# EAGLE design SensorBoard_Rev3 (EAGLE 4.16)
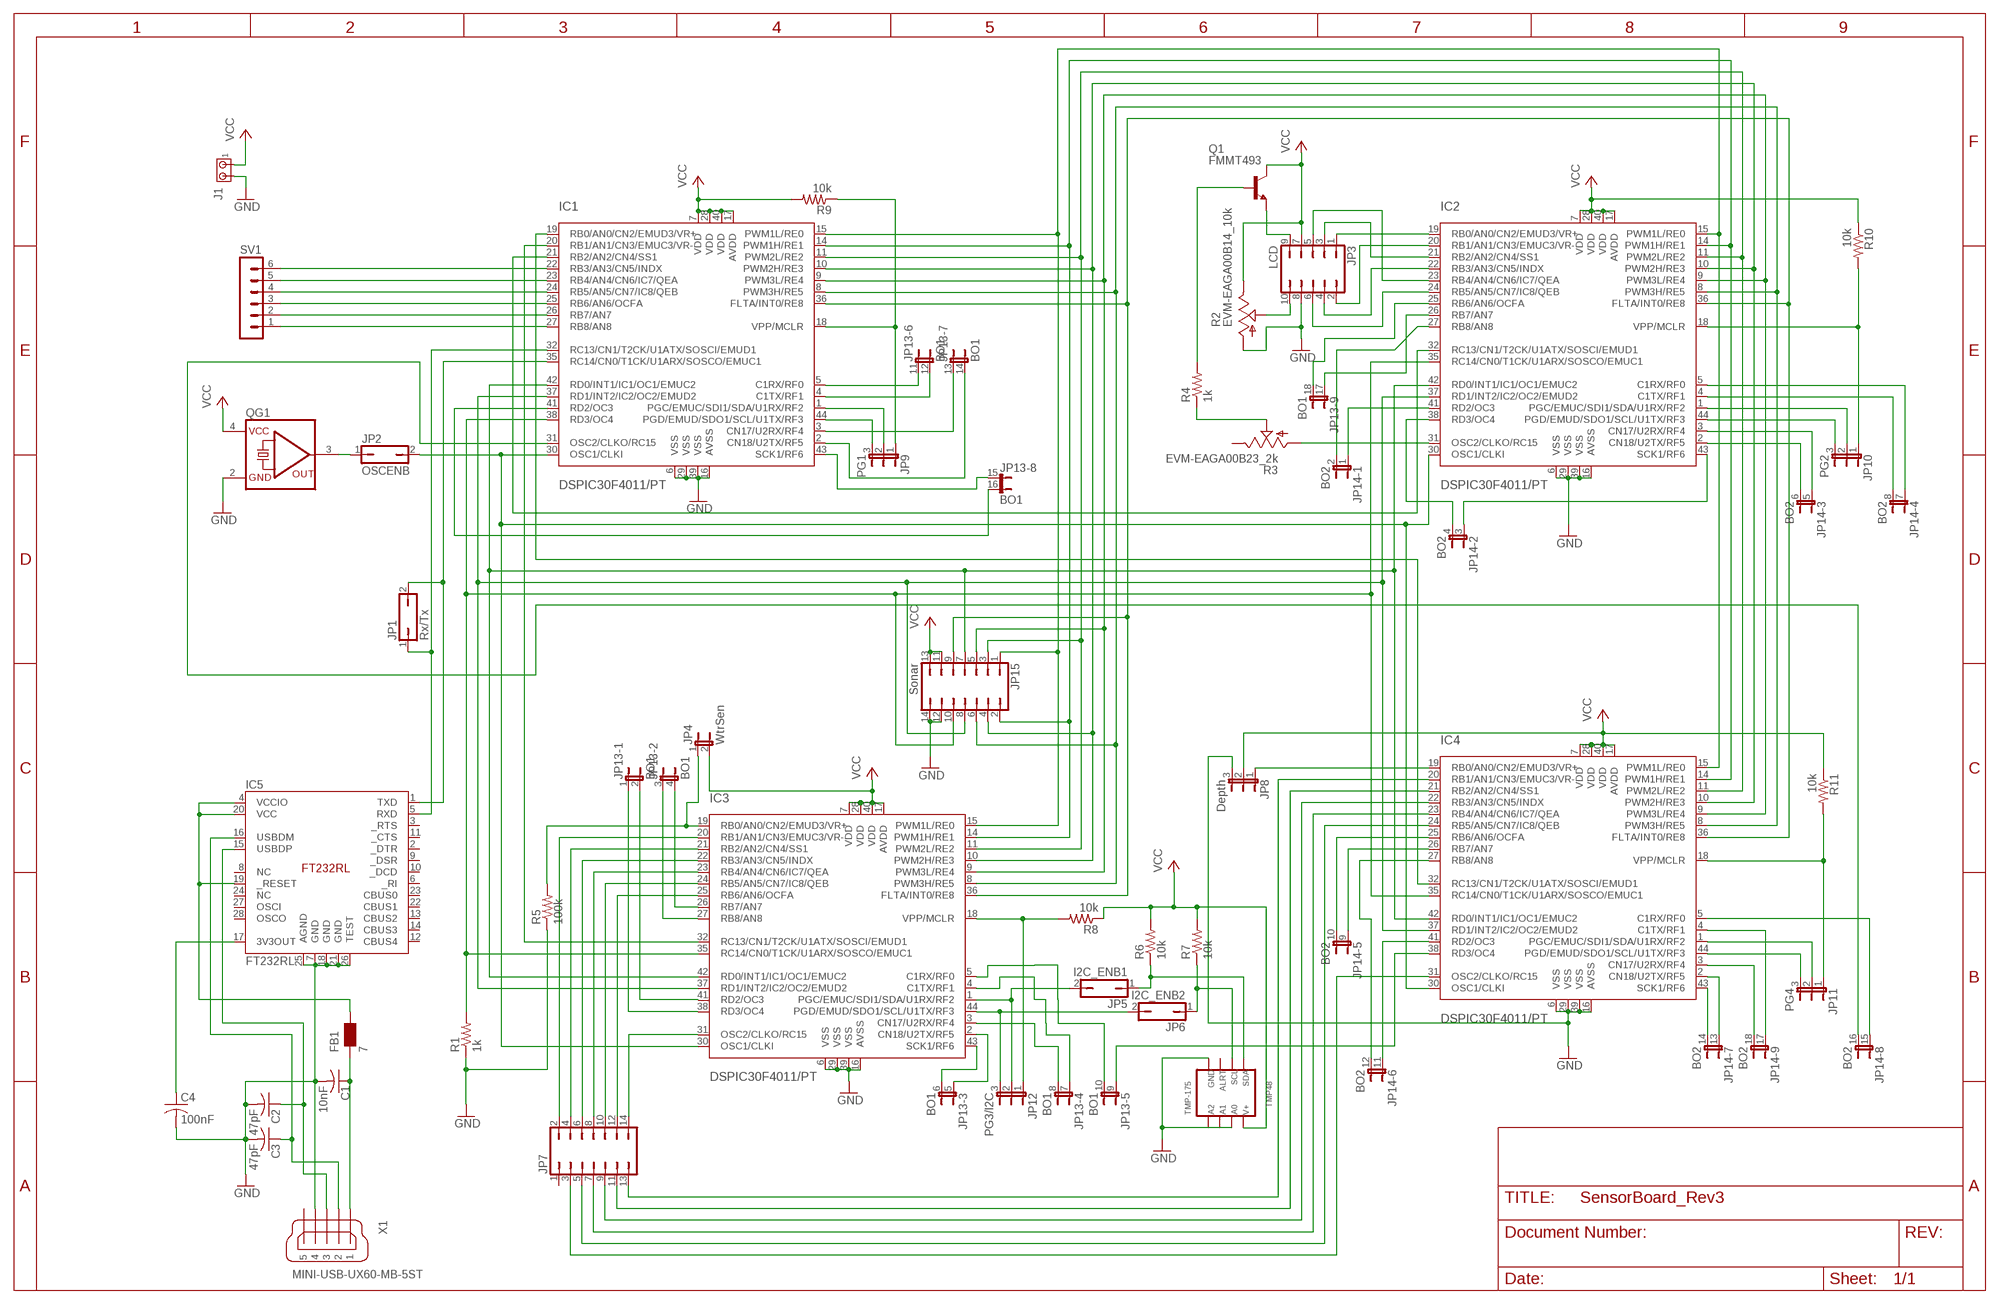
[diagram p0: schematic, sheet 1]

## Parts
C1  10nF  C-USC1206K  [C1206K]
C2  47pF  C-USC1206K  [C1206K]
C3  47pF  C-USC1206K  [C1206K]
C4  100nF  C-USC1206K  [C1206K]
FB1  7  WE-CBF_0805  [0805]
IC1  DSPIC30F4011/PT  [TQFP44]
IC2  DSPIC30F4011/PT  [TQFP44]
IC3  DSPIC30F4011/PT  [TQFP44]
IC4  DSPIC30F4011/PT  [TQFP44]
IC5  FT232RL  [SSOP-28]
J1  MTA02-156  [1X2MTA]
JP1  Rx/Tx  JP1Q  [JP1]
JP2  OSCENB  JP1Q  [JP1]
JP3  LCD  JP5Q  [JP5Q]
JP4  WtrSen  JP1E  [JP1]
JP5  I2C_ENB1  JP1Q  [JP1]
JP6  I2C_ENB2  JP1Q  [JP1]
JP7  JP7Q  [JP7Q]
JP8  Depth  JP2E  [JP2]
JP9  PG1  JP2E  [JP2]
JP10  PG2  JP2E  [JP2]
JP11  PG4  JP2E  [JP2]
JP12  PG3/I2C  JP2E  [JP2]
JP13  BO1  JP9QE  [JP9Q]
JP14  BO2  JP9QE  [JP9Q]
JP15  Sonar  JP7Q  [JP7Q]
Q1  FMMT493  -NPN-SOT23-EBC  [SOT23-EBC]
QG1  SG531  [DIL08-4]
R1  1k  R-US_R1206  [R1206]
R2  EVM-EAGA00B14_10k  TRIM_US-CT6  [CT6]
R3  EVM-EAGA00B23_2k  TRIM_US-CT6  [CT6]
R4  1k  R-US_R1206  [R1206]
R5  100k  R-US_R1206  [R1206]
R6  10k  R-US_R1206  [R1206]
R7  10k  R-US_R1206  [R1206]
R8  10k  R-US_R1206  [R1206]
R9  10k  R-US_R1206  [R1206]
R10  10k  R-US_R1206  [R1206]
R11  10k  R-US_R1206  [R1206]
SV1  MA06-1  [MA06-1]
TMP48  TMP-175  [SO-08]
X1  MINI-USB-UX60-MB-5ST  [UX60-MB-5ST]

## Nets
GND [4amps]: C1.2 C2.2 C3.2 C4.2 IC1.6(VSS) IC1.16(AVSS) IC1.29(VSS) IC1.39(VSS) IC2.6(VSS) IC2.16(AVSS) IC2.29(VSS) IC2.39(VSS) IC3.6(VSS) IC3.16(AVSS) IC3.29(VSS) IC3.39(VSS) IC4.6(VSS) IC4.16(AVSS) IC4.29(VSS) IC4.39(VSS) IC5.7(GND) IC5.18(GND) IC5.21(GND) IC5.25(AGND) IC5.26(TEST) J1.2 JP3.8 JP8.3 JP15.12 JP15.14 QG1.2(GND) R1.1 R2.A R5.1 TMP48.4 TMP48.5 TMP48.6 TMP48.7 X1.4
N$1: IC1.19(RB0/AN0/CN2/EMUD3/VR+) IC4.32(RC13/CN1/T2CK/U1ATX/SOSCI/EMUD1)
N$2: IC1.20(RB1/AN1/CN3/EMUC3/VR-) IC3.32(RC13/CN1/T2CK/U1ATX/SOSCI/EMUD1)
N$3: IC1.21(RB2/AN2/CN4/SS1) IC2.32(RC13/CN1/T2CK/U1ATX/SOSCI/EMUD1)
N$4: IC1.22(RB3/AN3/CN5/INDX) SV1.6
N$5: IC1.24(RB5/AN5/CN7/IC8/QEB) SV1.4
N$6: IC1.25(RB6/AN6/OCFA) SV1.3
N$7: IC1.26(RB7/AN7) SV1.2
N$8: IC1.27(RB8/AN8) SV1.1
N$9: IC1.30(OSC1/CLKI) IC2.30(OSC1/CLKI) IC3.30(OSC1/CLKI) IC4.30(OSC1/CLKI) JP2.2
N$10: C2.1 IC5.15(USBDP) X1.3
N$11: C1.1 FB1.1 X1.1
N$12: C3.1 IC5.16(USBDM) X1.2
N$13: C4.1 IC5.17(3V3OUT)
N$14: FB1.2 IC5.4(VCCIO) IC5.19(_RESET) IC5.20(VCC)
N$15: IC1.32(RC13/CN1/T2CK/U1ATX/SOSCI/EMUD1) IC5.5(RXD) JP1.1
N$16: IC1.35(RC14/CN0/T1CK/U1ARX/SOSCO/EMUC1) IC5.1(TXD) JP1.2
N$17: JP2.1 QG1.3(OUT)
N$18: IC1.23(RB4/AN4/CN6/IC7/QEA) SV1.5
N$19: IC1.15(PWM1L/RE0) IC2.15(PWM1L/RE0) IC3.15(PWM1L/RE0) IC4.15(PWM1L/RE0) JP15.1
N$20: IC1.14(PWM1H/RE1) IC2.14(PWM1H/RE1) IC3.14(PWM1H/RE1) IC4.14(PWM1H/RE1) JP15.2
N$21: IC1.11(PWM2L/RE2) IC2.11(PWM2L/RE2) IC3.11(PWM2L/RE2) IC4.11(PWM2L/RE2) JP15.3
N$22: IC1.10(PWM2H/RE3) IC2.10(PWM2H/RE3) IC3.10(PWM2H/RE3) IC4.10(PWM2H/RE3) JP15.4
N$23: IC1.9(PWM3L/RE4) IC2.9(PWM3L/RE4) IC3.9(PWM3L/RE4) IC4.9(PWM3L/RE4) JP15.5
N$24: IC1.8(PWM3H/RE5) IC2.8(PWM3H/RE5) IC3.8(PWM3H/RE5) IC4.8(PWM3H/RE5) JP15.6
N$25: IC1.42(RD0/INT1/IC1/OC1/EMUC2) IC2.42(RD0/INT1/IC1/OC1/EMUC2) IC3.42(RD0/INT1/IC1/OC1/EMUC2) IC4.42(RD0/INT1/IC1/OC1/EMUC2) JP15.7
N$26: IC1.37(RD1/INT2/IC2/OC2/EMUD2) IC2.37(RD1/INT2/IC2/OC2/EMUD2) IC3.37(RD1/INT2/IC2/OC2/EMUD2) IC4.37(RD1/INT2/IC2/OC2/EMUD2) JP15.8
N$27: IC1.38(RD3/OC4) IC2.35(RC14/CN0/T1CK/U1ARX/SOSCO/EMUC1) IC3.35(RC14/CN0/T1CK/U1ARX/SOSCO/EMUC1) IC4.35(RC14/CN0/T1CK/U1ARX/SOSCO/EMUC1) JP15.10 R1.2
N$28: IC1.36(FLTA/INT0/RE8) IC2.36(FLTA/INT0/RE8) IC3.36(FLTA/INT0/RE8) IC4.36(FLTA/INT0/RE8) JP15.9
N$29: IC2.19(RB0/AN0/CN2/EMUD3/VR+) JP3.1
N$30: IC2.20(RB1/AN1/CN3/EMUC3/VR-) JP3.2
N$31: IC2.21(RB2/AN2/CN4/SS1) JP3.3
N$32: IC2.22(RB3/AN3/CN5/INDX) JP3.4
N$33: IC2.23(RB4/AN4/CN6/IC7/QEA) JP3.5
N$34: IC2.24(RB5/AN5/CN7/IC8/QEB) JP3.6
N$35: JP3.10 R2.S
N$36: IC2.31(OSC2/CLKO/RC15) R3.A
N$37: R3.S R4.1
N$38: JP3.9 Q1.E
N$39: Q1.B R4.2
N$40: IC3.21(RB2/AN2/CN4/SS1) JP7.4
N$41: IC3.19(RB0/AN0/CN2/EMUD3/VR+) JP4.1 R5.2
N$42: IC3.22(RB3/AN3/CN5/INDX) JP7.6
N$43: JP6.1 R7.1 TMP48.2
N$44: JP5.1 R6.1 TMP48.1
N$45: IC3.1(PGC/EMUC/SDI1/SDA/U1RX/RF2) JP5.2 JP12.2
N$46: IC3.44(PGD/EMUD/SDO1/SCL/U1TX/RF3) JP6.2 JP12.3
N$47: IC3.23(RB4/AN4/CN6/IC7/QEA) JP7.8
N$48: IC3.24(RB5/AN5/CN7/IC8/QEB) JP7.10
N$49: IC3.25(RB6/AN6/OCFA) JP7.12
N$50: IC3.20(RB1/AN1/CN3/EMUC3/VR-) JP7.2
N$51: IC3.31(OSC2/CLKO/RC15) JP7.14
N$52: IC4.19(RB0/AN0/CN2/EMUD3/VR+) JP8.1
N$53: IC4.20(RB1/AN1/CN3/EMUC3/VR-) JP7.13
N$54: IC4.21(RB2/AN2/CN4/SS1) JP7.11
N$55: IC4.22(RB3/AN3/CN5/INDX) JP7.9
N$56: IC4.23(RB4/AN4/CN6/IC7/QEA) JP7.7
N$57: IC4.24(RB5/AN5/CN7/IC8/QEB) JP7.5
N$58: IC4.31(OSC2/CLKO/RC15) JP7.3
N$59: IC3.18(VPP/MCLR) JP12.1 R8.2
N$60: IC1.18(VPP/MCLR) JP9.1 R9.1
N$61: IC2.18(VPP/MCLR) JP10.1 R10.2
N$62: IC1.1(PGC/EMUC/SDI1/SDA/U1RX/RF2) JP9.2
N$63: IC1.44(PGD/EMUD/SDO1/SCL/U1TX/RF3) JP9.3
N$64: IC2.1(PGC/EMUC/SDI1/SDA/U1RX/RF2) JP10.2
N$65: IC2.44(PGD/EMUD/SDO1/SCL/U1TX/RF3) JP10.3
N$66: IC4.18(VPP/MCLR) JP11.1 R11.2
N$67: IC4.1(PGC/EMUC/SDI1/SDA/U1RX/RF2) JP11.2
N$68: IC4.44(PGD/EMUD/SDO1/SCL/U1TX/RF3) JP11.3
N$69: IC3.38(RD3/OC4) JP13.1
N$70: IC3.41(RD2/OC3) JP13.2
N$71: IC3.27(RB8/AN8) JP13.3
N$72: IC3.26(RB7/AN7) JP13.4
N$73: IC3.2(CN18/U2TX/RF5) JP13.5
N$74: IC3.43(SCK1/RF6) JP13.6
N$75: IC3.4(C1TX/RF1) JP13.7
N$76: IC3.3(CN17/U2RX/RF4) JP13.8
N$77: IC3.5(C1RX/RF0) JP13.10
N$78: IC1.43(SCK1/RF6) JP13.15
N$79: IC1.2(CN18/U2TX/RF5) JP13.14
N$80: IC1.3(CN17/U2RX/RF4) JP13.13
N$81: IC1.4(C1TX/RF1) JP13.12
N$82: IC1.5(C1RX/RF0) JP13.11
N$83: IC1.41(RD2/OC3) JP13.16
N$84: IC2.25(RB6/AN6/OCFA) JP13.18
N$85: IC2.26(RB7/AN7) JP13.17
N$86: IC2.27(RB8/AN8) JP14.2
N$87: IC2.41(RD2/OC3) JP14.1
N$88: IC2.38(RD3/OC4) JP14.4
N$89: IC2.43(SCK1/RF6) JP14.3
N$90: IC2.2(CN18/U2TX/RF5) JP14.6
N$91: IC2.3(CN17/U2RX/RF4) JP14.5
N$92: IC2.5(C1RX/RF0) JP14.7
N$93: IC2.4(C1TX/RF1) JP14.8
N$94: IC4.25(RB6/AN6/OCFA) JP14.10
N$95: IC4.26(RB7/AN7) JP14.9
N$96: IC4.27(RB8/AN8) JP14.12
N$97: IC4.41(RD2/OC3) JP14.11
N$98: IC4.43(SCK1/RF6) JP14.14
N$99: IC4.2(CN18/U2TX/RF5) JP14.13
N$100: IC4.3(CN17/U2RX/RF4) JP14.18
N$101: IC4.4(C1TX/RF1) JP14.17
N$102: IC4.5(C1RX/RF0) JP14.15
N$103: IC4.38(RD3/OC4) JP13.9
N$104: IC1.31(OSC2/CLKO/RC15) JP14.16
VCC [4amps]: IC1.7(VDD) IC1.17(AVDD) IC1.28(VDD) IC1.40(VDD) IC2.7(VDD) IC2.17(AVDD) IC2.28(VDD) IC2.40(VDD) IC3.7(VDD) IC3.17(AVDD) IC3.28(VDD) IC3.40(VDD) IC4.7(VDD) IC4.17(AVDD) IC4.28(VDD) IC4.40(VDD) J1.1 JP3.7 JP4.2 JP8.2 JP15.11 JP15.13 Q1.C QG1.4(VCC) R2.E R6.2 R7.2 R8.1 R9.2 R10.1 R11.1 TMP48.8
Unconnected: IC5.2(_DTR) IC5.3(_RTS) IC5.6(_RI) IC5.8(NC) IC5.9(_DSR) IC5.10(_DCD) IC5.11(_CTS) IC5.12(CBUS4) IC5.13(CBUS2) IC5.14(CBUS3) IC5.22(CBUS1) IC5.23(CBUS0) IC5.24(NC) IC5.27(OSCI) IC5.28(OSCO) JP7.1 R3.E TMP48.3 X1.5

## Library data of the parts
C1-C4 = rcl:C-US: CAPACITOR, American symbol
FB1 = wuerth-elektronik:WE-CBF: SMD EMI Suppression Ferrite Beads
IC1-IC4 = microchip-dspic:DSPIC30F4011: dsPIC Motion Controller DSC
IC5 = ftdi4:FT232RL
J1 = con-amp:MTA02-156: AMP connector
JP1 JP2 JP5 JP6 = jumper:JP1Q: JUMPER
JP3 = jumper:JP5Q: JUMPER
JP4 = jumper:JP1E: JUMPER
JP7 JP15 = jumper:JP7Q: JUMPER
JP8-JP12 = jumper:JP2E: JUMPER
JP13 JP14 = jumper:JP9QE: JUMPER
Q1 = transistor:*-NPN-: NPN Transistror
QG1 = crystal:SG531: CRYSTAL RESONATOR
R1 R4-R11 = rcl:R-US_: RESISTOR, American symbol
R2 R3 = pot:TRIM_US-: POTENTIOMETER
SV1 = con-lstb:MA06-1: PIN HEADER
TMP48 = texas:TMP-175
X1 = con-hirose:MINI-USB-: MINI USB Connector Source: http://www.hirose.co.jp/cataloge_hp/e24000019.pdf

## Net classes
0 default: width 0.178 mm
1 2amps: width 0.178 mm
2 4amps: width 0.533 mm

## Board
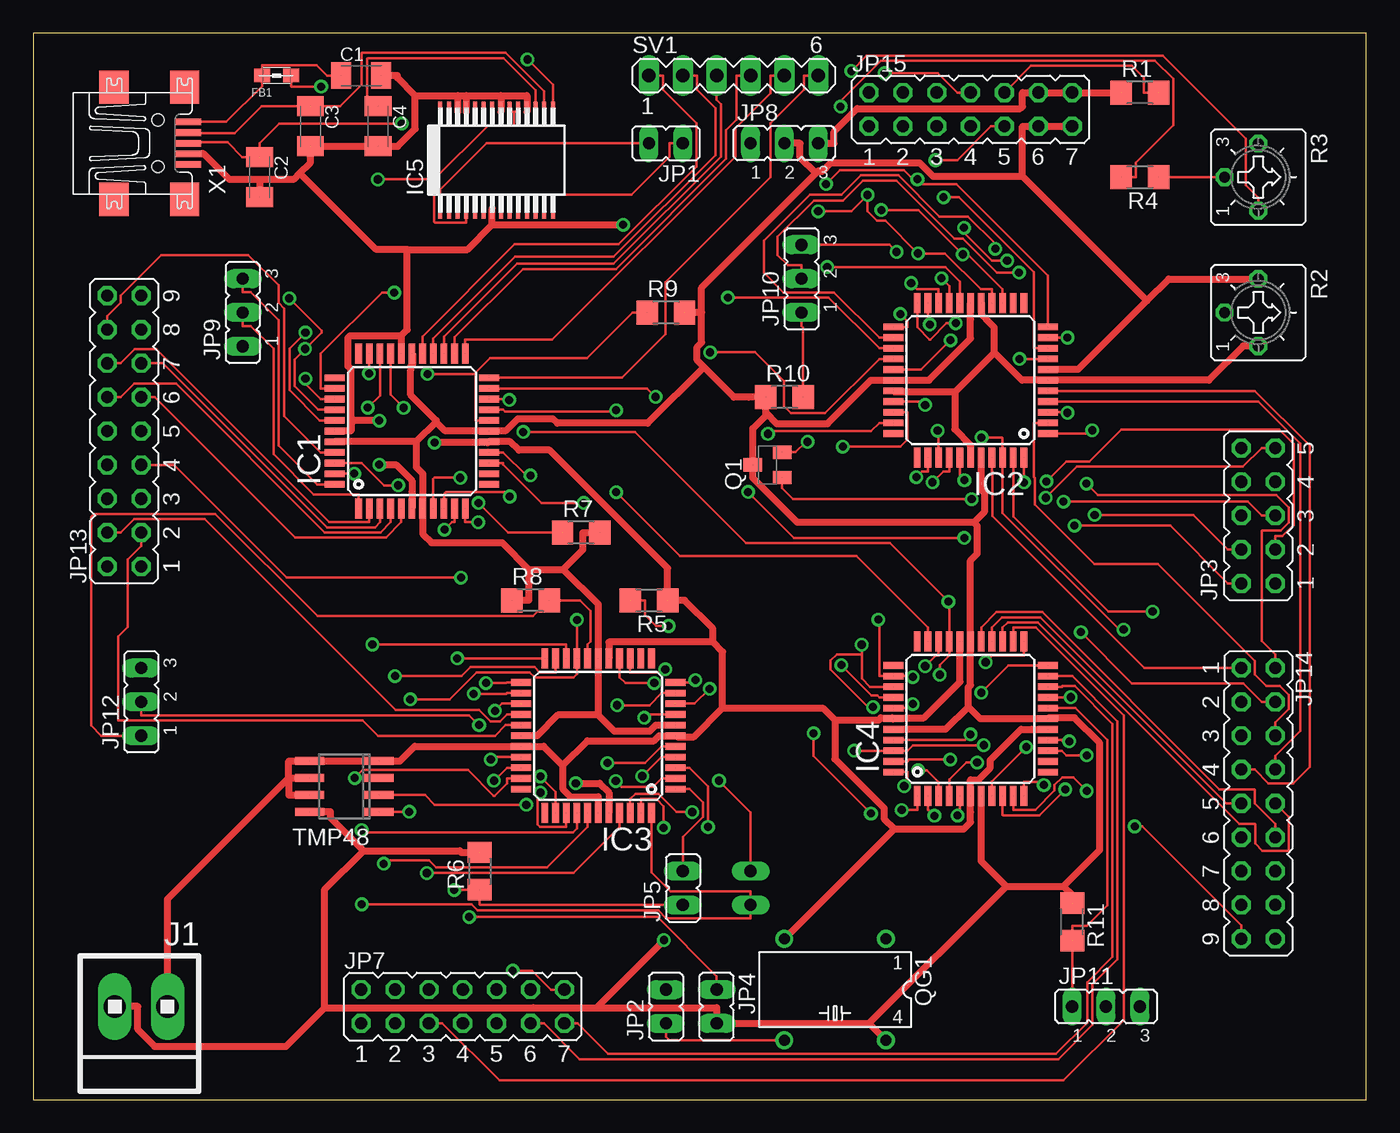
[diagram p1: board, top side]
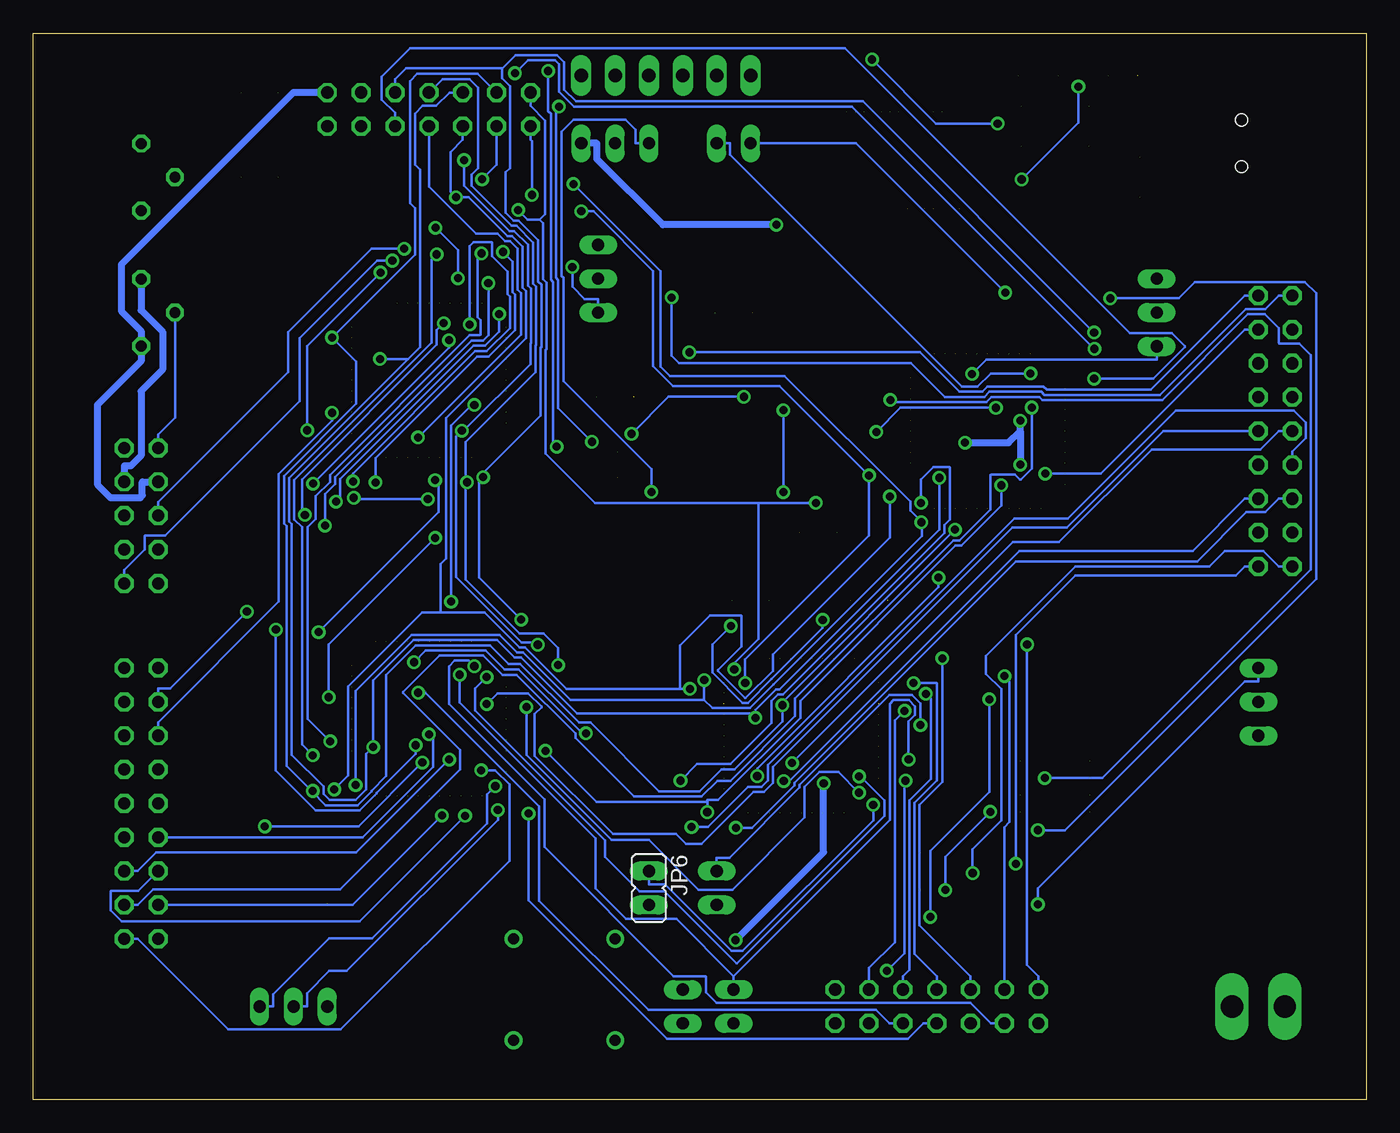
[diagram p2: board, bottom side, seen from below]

Size 100 x 80 mm. Coordinates in mm from the lower left corner, seen from the top.
Outline: 0,0 100,0 100,80 0,80 0,0
Copper layers (1*16): Top 0.035mm / dielectric 1.5mm / Bottom 0.035mm
Design rules "default": minimum track width 10mil, minimum drill 24mil, track to track 8mil, track to pad 8mil, pad to pad 8mil, via to via 8mil, smd to smd 8mil, copper to edge 40mil, drill to drill 8mil, minimum pad ring 10mil, minimum via ring 8mil, stop-mask expansion 4mil, vias tented up to drill 0mil, thermal gap 10mil

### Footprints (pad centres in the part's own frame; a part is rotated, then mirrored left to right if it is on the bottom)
C1206K = smd 1.5 x 2: 1 -1.5,0; 2 1.5,0
0805 = smd 1.2 x 1: 1 -1.1,0; 2 1.1,0
TQFP44 = smd 1.5 x 0.5: 1 -5.8,4; 2 -5.8,3.2; 3 -5.8,2.4; 4 -5.8,1.6; 5 -5.8,0.8; 6 -5.8,0; 7 -5.8,-0.8; 8 -5.8,-1.6; 9 -5.8,-2.4; 10 -5.8,-3.2; 11 -5.8,-4; 23 5.8,-4; 24 5.8,-3.2; 25 5.8,-2.4; 26 5.8,-1.6; 27 5.8,-0.8; 28 5.8,0; 29 5.8,0.8; 30 5.8,1.6; 31 5.8,2.4; 32 5.8,3.2; 33 5.8,4 | smd 0.5 x 1.5: 12 -4,-5.8; 13 -3.2,-5.8; 14 -2.4,-5.8; 15 -1.6,-5.8; 16 -0.8,-5.8; 17 0,-5.8; 18 0.8,-5.8; 19 1.6,-5.8; 20 2.4,-5.8; 21 3.2,-5.8; 22 4,-5.8; 34 4,5.8; 35 3.2,5.8; 36 2.4,5.8; 37 1.6,5.8; 38 0.8,5.8; 39 0,5.8; 40 -0.8,5.8; 41 -1.6,5.8; 42 -2.4,5.8; 43 -3.2,5.8; 44 -4,5.8
SSOP-28 = smd 0.3 x 1.5: 1 -4.225,-3.625; 2 -3.575,-3.625; 3 -2.925,-3.625; 4 -2.275,-3.625; 5 -1.625,-3.625; 6 -0.975,-3.625; 7 -0.325,-3.625; 8 0.325,-3.625; 9 0.975,-3.625; 10 1.625,-3.625; 11 2.275,-3.625; 12 2.925,-3.625; 13 3.575,-3.625; 14 4.225,-3.625; 15 4.225,3.625; 16 3.575,3.625; 17 2.925,3.625; 18 2.275,3.625; 19 1.625,3.625; 20 0.975,3.625; 21 0.325,3.625; 22 -0.325,3.625; 23 -0.975,3.625; 24 -1.625,3.625; 25 -2.275,3.625; 26 -2.925,3.625; 27 -3.575,3.625; 28 -4.225,3.625
1X2MTA = drill 1.676 long: 1 1.981,0; 2 -1.981,0
JP1 = drill 0.914 long: 1 0,-1.27; 2 0,1.27
JP5Q = drill 0.914 octagon: 1 -5.08,-1.27; 2 -5.08,1.27; 3 -2.54,-1.27; 4 -2.54,1.27; 5 0,-1.27; 6 0,1.27; 7 2.54,-1.27; 8 2.54,1.27; 9 5.08,-1.27; 10 5.08,1.27
JP7Q = drill 0.914 octagon: 1 -7.62,-1.27; 2 -7.62,1.27; 3 -5.08,-1.27; 4 -5.08,1.27; 5 -2.54,-1.27; 6 -2.54,1.27; 7 0,-1.27; 8 0,1.27; 9 2.54,-1.27; 10 2.54,1.27; 11 5.08,-1.27; 12 5.08,1.27; 13 7.62,-1.27; 14 7.62,1.27
JP2 = drill 0.914 long: 1 -2.54,0; 2 0,0; 3 2.54,0
JP9Q = drill 0.914 octagon: 1 -10.16,-1.27; 2 -10.16,1.27; 3 -7.62,-1.27; 4 -7.62,1.27; 5 -5.08,-1.27; 6 -5.08,1.27; 7 -2.54,-1.27; 8 -2.54,1.27; 9 0,-1.27; 10 0,1.27; 11 2.54,-1.27; 12 2.54,1.27; 13 5.08,-1.27; 14 5.08,1.27; 15 7.62,-1.27; 16 7.62,1.27; 17 10.16,-1.27; 18 10.16,1.27
SOT23-EBC = smd 1 x 1.4: B 0.95,-1.1; C 0,1.1; E -0.95,-1.1
DIL08-4 = drill 0.813 round: 1 -3.81,-3.81; 2 3.81,-3.81; 3 3.81,3.81; 4 -3.81,3.81
R1206 = smd 1.6 x 1.8: 1 -1.4,0; 2 1.4,0
CT6 = drill 0.813 octagon: A 2.515,0; E -2.515,0; S 0,-2.54
MA06-1 = drill 1.016 long: 1 -6.35,0; 2 -3.81,0; 3 -1.27,0; 4 1.27,0; 5 3.81,0; 6 6.35,0
SO-08 = smd 0.6 x 2.2: 1 -1.905,-2.6; 2 -0.635,-2.6; 3 0.635,-2.6; 4 1.905,-2.6; 5 1.905,2.6; 6 0.635,2.6; 7 -0.635,2.6; 8 -1.905,2.6
UX60-MB-5ST = smd 2 x 0.5: 1 2.25,1.6; 2 2.25,0.8; 3 2.25,0; 4 2.25,-0.8; 5 2.25,-1.6 | smd 2.2 x 2.5: M1 -3.3,-4.2; M2 -3.3,4.2; M3 2,4.2; M4 2,-4.2 | hole 0.9: 0,-1.75; 0,1.75

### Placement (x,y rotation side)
C1  24.6,76.83 0 top
C2  16.98,69.21 270 top
C3  20.79,73.02 270 top
C4  25.87,73.02 270 top
FB1  18.25,76.83 0 top
IC1  28.41,50.16 90 top
IC2  70.32,53.97 180 top
IC3  42.38,27.3 180 top
IC4  70.32,28.57 90 top
IC5  34.76,70.48 0 top
J1  8.09,6.98 180 top
JP1  47.46,71.75 90 top
JP2  47.46,6.98 0 top
JP3  91.91,43.81 90 top
JP4  51.27,6.98 180 top
JP5  48.73,15.87 0 top
JP6  53.81,15.87 180 bottom
JP7  32.22,6.98 0 top
JP8  56.35,71.75 0 top
JP9  15.71,59.05 90 top
JP10  57.62,61.59 90 top
JP11  80.48,6.98 0 top
JP12  8.09,29.84 90 top
JP13  6.82,50.16 90 top
JP14  91.91,22.22 270 top
JP15  70.32,74.29 0 top
Q1  55.08,47.62 90 top
QG1  60.16,8.25 180 top
R1  83.02,75.56 0 top
R2  91.91,59.05 270 top
R3  91.91,69.21 270 top
R4  83.02,69.21 180 top
R5  46.19,37.46 180 top
R6  33.49,17.14 90 top
R7  41.11,42.54 0 top
R8  37.3,37.46 0 top
R9  47.46,59.05 0 top
R10  56.35,52.7 0 top
R11  77.94,13.33 270 top
SV1  52.54,76.83 0 top
TMP48  23.33,23.49 90 top
X1  9.36,71.75 0 top

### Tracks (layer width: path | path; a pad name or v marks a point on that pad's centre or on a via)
GND  (via drill 0.61 pad 1.02)  (31 unrouted)
  Top 0.127: X1.4 11.62,70.96 12.6,70.96
  Top 0.498: 48.34,27.22 48.33,27.22 48.26,27.3 | 64.44,28.65 64.44,28.57 | 71.47,58.54 71.47,58.56 71.16,58.87 | 64.62,53.09 64.61,53.09 64.54,53.17 | 34.11,49.28 34.12,49.28 34.19,49.36
  Top 0.533: 16.98,69.03 14.73,69.03 12.79,70.96 12.6,70.96 | 16.98,69.03 16.98,68.93 | 20,69.5 19.53,69.03 16.98,69.03 | 19.16,24.12 19.16,22.86 TMP48.7 | 19.16,24.12 TMP48.6 19.16,24.12 | 19.16,24.12 19.16,25.39 TMP48.5 TMP48.4 27.5,25.39 28.61,26.5 IC3.29 38.29,26.5 39.72,25.06 | R2.A 90.78,56.54 88.21,53.97 IC2.6 74.18,53.97 72.09,56.05 | R1.1 JP15.14 JP15.12 74.22,75.56 74.22,74.53 74.04,74.35 61.81,74.35 60.07,72.62 60.07,71.75 JP8.3 | 31.83,75.33 32.48,75.33 | IC5.25 32.48,75.14 32.48,75.33 | 32.48,75.33 35.09,75.33 | IC5.21 35.09,75.14 35.09,75.33 | 35.09,75.33 37.04,75.33 IC5.18 | IC5.26 31.83,75.14 31.83,75.33 | 34.44,65.63 IC5.7 | 64.44,28.57 IC4.39 | IC3.39 42.38,22.72 40.32,22.72 39.72,23.32 39.72,25.06 | 48.26,27.3 IC3.6 46.96,27.3 46.57,26.91 41.57,26.91 39.72,25.06 | IC2.16 71.16,59.73 71.16,58.87 | IC1.39 23.83,50.16 23.83,51.17 | 28.65,75.33 31.83,75.33 | 28.65,75.33 27.32,76.66 27.32,76.83 C1.2 | 28.65,75.33 28.65,72.83 27.34,71.52 C4.2 C3.2 20.79,70.3 20,69.5 | 64.54,53.17 IC2.29 | IC4.16 74.9,27.77 74.1,27.77 71.79,25.47 71.79,24.88 70.9,23.99 70.32,23.99 IC4.6 70.32,21.55 70.32,20.8 69.82,20.3 64.59,20.3 | IC3.16 43.18,34.32 50.99,34.32 | 50.99,34.32 50.99,35.34 48.86,37.46 R5.1 47.59,39.87 38.74,48.72 36.43,48.72 35.79,49.36 IC1.16 34.19,49.36 | 16.98,68.93 C2.2 | 34.11,49.28 v30.1,49.28 | 34.44,65.63 v44.25,65.63 | IC1.6 28.41,45.58 28.41,46.44 27.21,47.63 v25.95,47.63 | 27.61,57.31 IC1.29 | 64.59,20.3 QG1.2 | 16.98,68.93 C2.2 | 27.61,57.31 28.06,57.76 28.06,63.78 | 34.44,65.63 32.58,63.78 28.06,63.78 | 28.06,63.78 25.72,63.78 20,69.5 | 16.98,68.93 C2.2 | 51.72,29.38 51.72,33.59 50.99,34.32
  Top 0.533: 23.83,51.17 23.83,54.8 23.6,55.03 23.6,57.16 23.75,57.31 27.61,57.31 | 16.98,68.93 C2.2 | 69.13,53.09 64.62,53.09 | 16.98,68.93 C2.2 | 19.16,24.12 10.07,15.04 J1.2 | 16.98,68.93 C2.2 | 69.13,53.09 69.13,50.3 70.32,49.11 IC2.39 | 16.98,68.93 C2.2 | 72.09,56.05 69.13,53.09 | 72.09,56.05 72.09,57.92 71.47,58.54 | 16.98,68.93 C2.2 | 23.83,51.17 24.07,50.94 v25.95,50.94 | 16.98,68.93 C2.2 | 16.98,68.93 C2.2 | 51.72,29.38 49.56,27.22 48.34,27.22 | 16.98,68.93 C2.2 | 16.98,68.93 C2.2 | 16.98,68.93 C2.2 | 16.98,68.93 C2.2 | 16.98,68.93 C2.2 | 16.98,68.93 C2.2 | IC4.29 69.52,31.35 66.82,28.65 64.44,28.65 63.58,28.65 63.41,28.47 60.13,28.47 | 16.98,68.93 C2.2 | 64.59,20.3 63.82,21.07 63.82,21.86 60.13,25.55 60.13,28.47 | 60.13,28.47 59.23,29.38 51.72,29.38 | 16.98,68.93 C2.2 | 16.98,68.93 C2.2
  Bottom 0.533: JP15.14 80.49,75.56 93.4,62.65 93.4,59.16 91.91,57.67 R2.A 91.91,55.4 95.2,52.11 95.2,46.15 94.22,45.17 91.98,45.17 91.82,45.32 91.82,46.35 JP3.8 | JP8.3 57.71,71.75 57.71,70.57 52.77,65.63 v44.25,65.63 | 25.95,50.17 v25.95,47.63 | 25.95,50.17 26.83,49.28 v30.1,49.28 | 25.95,50.17 v25.95,50.94
N$1  (via drill 0.61 pad 1.02)  (2 unrouted)
  Top 0.178: IC1.19 35.25,51.76 35.39,51.63 43.62,51.63 v43.72,51.73 | IC4.32 67.12,35.41 61.74,40.79 48.5,40.79 v43.72,45.57
  Bottom 0.178: v43.72,45.57 v43.72,51.73
N$2  (via drill 0.61 pad 1.02)  (2 unrouted)
  Top 0.178: v35.7,52.48 35.62,52.56 IC1.20 | v24.11,24.12 24.71,24.72 32.61,24.72 34.54,22.79 34.59,22.79 35.54,23.73 35.54,24.1 IC3.32
  Bottom 0.178: v24.11,24.12 19.8,24.12 4.14,39.78 4.14,55.86 5.01,56.73 6.51,56.73 6.56,56.78 6.56,57.87 7.61,58.93 8.87,58.93 15.31,52.48 24.29,52.48 24.52,52.72 28.11,52.72 28.49,52.34 35.55,52.34 v35.7,52.48
N$3  (via drill 0.61 pad 1.02)  (2 unrouted)
  Top 0.178: IC2.32 63.48,50.77 62.86,50.15 55.32,50.15 v55.12,49.95 | IC1.21 46.05,53.36 v46.69,52.73
  Bottom 0.178: v55.12,49.95 52.34,52.73 v46.69,52.73
N$4  (1 unrouted)
  Top 0.178: IC1.22 44.16,54.16 47.44,57.45 47.44,61.34 55.32,69.21 55.32,73.26 57.83,75.77 57.83,76.83 SV1.6
N$5  (1 unrouted)
  Top 0.178: SV1.4 52.75,76.83 52.75,73.5 51.97,72.72 51.97,70.59 43.7,62.32 36.74,62.32 31.61,57.2 IC1.24
N$6  (1 unrouted)
  Top 0.178: SV1.3 51.27,75.01 51.59,74.69 51.59,70.75 43.55,62.71 36.28,62.71 30.81,57.24 IC1.25
N$7  (1 unrouted)
  Top 0.178: SV1.2 49.79,76.83 49.79,75.77 51.17,74.39 51.17,70.87 43.52,63.23 36.13,63.23 30.01,57.1 IC1.26
N$8  (1 unrouted)
  Top 0.178: SV1.1 47.25,76.83 47.25,75.77 49.75,73.27 49.75,69.99 43.92,64.17 36.12,64.17 29.21,57.26 IC1.27
N$9  (via drill 0.61 pad 1.02)  (4 unrouted)
  Top 0.178: IC3.30 34.51,25.7 v34.33,25.51 | v36.75,50.08 45.13,50.08 53.46,41.75 64.27,41.75 v68.66,37.37 68.72,37.3 IC4.30 68.72,33.33 68.01,32.62 v68.01,31.88 | IC1.30 26.81,52.88 v27.78,51.9 | IC2.30 66.65,52.37 v66.91,52.11
  Bottom 0.178: JP2.2 47.46,9.26 | JP2.2 47.46,9.26 | JP2.2 47.46,9.26 | v34.33,25.51 34.33,28.35 33.84,28.84 33.84,29.5 34.31,29.97 35.46,29.97 35.75,29.68 35.75,20.97 47.46,9.26 | v36.75,50.08 34.93,51.9 v27.78,51.9 | v68.66,37.37 68.66,50.57 67.11,52.11 v66.91,52.11 | 47.46,9.26 51.75,13.55 55.52,13.55 57.82,15.85 57.82,19.6 68.01,29.8 v68.01,31.88
N$10  (via drill 0.61 pad 1.02)  (2 unrouted)
  Top 0.127: X1.3 11.47,71.82 11.87,71.82
  Top 0.178: 11.87,71.82 14.58,71.82 15.69,70.71 C2.1 16.98,71.75 18.45,73.23 v27.64,73.23 | IC5.15 38.98,76.13 v37.08,78.04
  Bottom 0.178: v27.64,73.23 32.26,73.23 v37.08,78.04
N$11  (2 unrouted)
  Top 0.127: X1.1 11.62,73.37 12.57,73.37
  Top 0.178: 12.57,73.37 14.49,73.37 17.15,76.03 FB1.1 17.15,77.62 21.26,77.62 22.05,76.83 C1.1
N$12  (2 unrouted)
  Top 0.127: X1.2 11.4,72.51 11.83,72.51
  Top 0.178: 11.83,72.51 15.12,72.51 17.13,74.52 19.49,74.52 C3.1 23.02,74.52 24.64,76.14 24.64,78.51 24.68,78.56 35.42,78.56 38.33,75.65 IC5.16
N$13  (2 unrouted)
  Top 0.178: C4.1 25.04,75.35 25.04,78.08 25.11,78.14 35.28,78.14 37.69,75.73 IC5.17
N$14  (via drill 0.61 pad 1.02)  (4 unrouted)
  Top 0.178: 36.06,74.1 IC5.20 | 36.06,74.1 IC5.19 | IC5.4 32.48,65.81 30.13,65.81 30.09,65.86 30.09,69.04 | 30.09,69.04 34.1,73.06 36.01,73.06 36.06,73.11 36.06,74.1 | v21.59,76.01 19.38,76.01 19.35,76.03 FB1.2 | v25.85,69.04 30.09,69.04
  Bottom 0.178: v21.59,76.01 21.59,73.29 v25.85,69.04
N$15  (via drill 0.61 pad 1.02)  (2 unrouted)
  Top 0.178: JP1.1 47.72,71.75 47.72,70.74 44.88,67.9 33.13,67.9 IC5.5 | v25.18,54.48 25.21,54.51 IC1.32
  Bottom 0.178: v25.18,54.48 28.16,54.48 29.15,53.49 30.33,53.49 47.72,70.88 47.72,71.75 JP1.1
N$16  (via drill 0.61 pad 1.02)  (2 unrouted)
  Top 0.178: JP1.2 34.02,71.75 30.54,68.27 IC5.1 | IC1.35 21.57,53.36 21.57,55.96 26.15,60.54 v27.08,60.54
  Bottom 0.178: v27.08,60.54 38.29,71.75 JP1.2
N$17
  Top 0.178: QG1.3 47.72,4.44 47.46,4.7 JP2.1
N$18  (1 unrouted)
  Top 0.178: SV1.5 55.29,76.83 55.29,75.5 52.67,72.88 52.67,70.75 38.92,57 32.41,57 IC1.23
N$19  (via drill 0.61 pad 1.02)  (4 unrouted)
  Top 0.178: IC2.15 71.92,60.81 71.08,60.81 68.4,63.49 v66.38,63.49 63.93,65.94 63.3,65.94 62.59,66.64 v62.59,67.87 61.37,66.65 v58.89,66.65 | v37.3,46.83 36.99,46.83 35.25,48.56 IC1.15 | v77.72,26.88 77.26,26.88 77.16,26.97 IC4.15 | v46.59,31.25 44.42,31.25 43.98,31.68 IC3.15
  Bottom 0.178: v46.59,31.25 46.59,33.03 37.3,42.32 v37.3,46.83 44.01,53.53 52.01,53.53 53.5,55.02 53.5,62.17 57.97,66.65 v58.89,66.65 | v62.59,67.87 62.59,71.91 62.7,72.01 JP15.1 | v66.38,63.49 66.67,63.19 66.67,58.69 66.46,58.48 66.46,57.39 66.51,57.34 67.27,57.34 77.75,46.86 77.75,46.34 78.82,45.27 78.82,43.54 79.41,42.95 79.41,28.56 v77.72,26.88
N$20  (via drill 0.61 pad 1.02)  (4 unrouted)
  Top 0.178: IC1.14 35.25,47.76 35.25,47.64 38.12,44.77 v41.29,44.77 | IC3.14 44.78,32.05 47.19,32.05 v47.41,32.27 | IC4.14 77.16,26.17 77.51,25.82 v79.03,25.82 | IC2.14 72.72,60.81 70.12,63.41 v69.73,63.41 66.4,66.74 v63.63,66.74
  Bottom 0.178: JP15.2 62.7,74.55 61.6,73.45 61.6,66.44 62.01,66.03 | 45.6,44.77 v41.29,44.77 | v47.41,32.27 47.41,32.75 45.6,34.56 45.6,44.77 | 62.01,66.03 62.92,66.03 v63.63,66.74 | 45.6,44.77 57.84,44.77 61.55,48.48 61.55,56.25 61.5,56.3 61.5,61.3 61.74,61.54 61.74,65.76 62.01,66.03 | v79.03,25.82 79.84,26.63 79.84,42.94 80.43,43.54 80.43,46.47 70.11,56.79 70.11,63.03 v69.73,63.41
N$21  (via drill 0.61 pad 1.02)  (4 unrouted)
  Top 0.178: IC1.11 32.41,43.32 v33.37,43.32 | IC4.11 74.32,23.81 75.61,23.81 v75.82,23.6 | IC3.11 49.22,31.3 49.39,31.47 v49.67,31.47 | 66.33,68.7 v66.33,69.05 | IC2.11 76.12,61.84 69.26,68.7 66.33,68.7 | 66.33,68.7 65.3,69.73 60.51,69.73 v59.47,68.69
  Bottom 0.178: JP15.3 65.24,72.01 65.24,70.14 v66.33,69.05 | 49.67,29.99 v49.67,31.47 | v33.37,43.32 33.34,43.32 | 49.67,29.99 49.05,29.37 46.24,29.37 44.45,31.16 33.34,42.27 33.34,43.32 | 33.34,43.32 34.21,44.18 34.21,44.86 43.64,54.3 52.23,54.3 52.93,54.99 52.93,62.14 v59.47,68.69 | v75.82,23.6 75.82,30.65 71.62,34.85 65,34.85 63.69,33.54 63.25,33.54 59.69,29.99 49.67,29.99
N$22  (via drill 0.61 pad 1.02)  (4 unrouted)
  Top 0.178: IC4.10 73.52,21.73 75.17,21.73 76.62,23.18 76.62,23.6 77.19,24.17 78.02,24.17 v79.03,23.15 | IC3.10 47.13,30.5 46.21,29.59 v43.8,29.59 | v30.84,42.76 31.4,43.32 31.61,43.32 IC1.10 | v77.59,57.17 IC2.10
  Bottom 0.178: v30.84,42.76 43.8,29.79 v43.8,29.59 43.8,28.37 47.39,24.78 48.36,24.78 50.02,23.12 53.05,23.12 58.2,28.28 59.06,28.28 63.48,32.7 64.35,32.7 65.74,34.08 71.31,34.08 73.52,31.87 73.52,24.27 74.63,23.15 74.63,23.11 75.66,22.08 78.06,22.08 79.13,23.15 | 79.13,23.15 v79.03,23.15 | JP15.4 66.66,76.97 71.19,76.97 71.75,76.42 71.75,67.27 71.36,66.89 71.36,63.4 v77.59,57.17 75.77,55.35 75.77,52.21 81.2,46.79 81.2,43.22 81,43.03 81,25.03 79.13,23.15
N$23  (via drill 0.61 pad 1.02)  (4 unrouted)
  Top 0.178: IC2.9 75.08,56.37 75.08,62.07 69.44,67.7 v68.29,67.7 | IC3.9 49.62,29.7 v50.74,30.81 | IC1.9 30.81,45.41 30.97,45.57 35.41,45.57 v35.74,45.24 | IC4.9 72.72,21.37 72.77,21.33 75.48,21.33 v77.43,23.27
  Bottom 0.178: JP15.5 67.78,72.01 68.7,71.1 68.7,68.11 v68.29,67.7 67.35,67.7 64.43,64.78 64.07,64.78 63.28,63.99 63.28,60.91 63.04,60.67 63.04,57.12 69.04,51.12 69.04,40.59 69.46,40.18 69.46,36.53 | 51.49,30.81 v50.74,30.81 | 51.49,30.81 51.49,34.06 49.21,36.34 46.91,36.34 46.86,36.29 46.86,33.99 48.63,32.22 48.63,32.15 46.62,30.14 46.55,30.14 44.52,32.17 44.52,33.39 35.74,42.17 v35.74,45.24 | 69.46,36.53 66.13,36.53 63.53,33.92 63.09,33.92 59.98,30.81 51.49,30.81 | 69.46,36.53 70.83,36.53 76.37,30.99 76.37,24.33 v77.43,23.27
N$24  (via drill 0.61 pad 1.02)  (4 unrouted)
  Top 0.178: IC4.8 71.92,23.88 v74.5,26.45 | IC3.8 46.08,28.9 v45.82,28.64 | IC1.8 30.01,46.56 30.1,46.65 v32.03,46.65 | v73.98,55.57 IC2.8
  Bottom 0.178: JP15.6 68.79,75.56 69.79,74.55 70.79,74.55 71.36,73.98 71.36,70.13 70.98,69.75 70.98,56.46 71.87,55.57 | v45.82,28.64 45.82,28.96 | 45.82,28.96 45.82,29.24 44.3,30.77 44.01,30.77 32.03,42.75 v32.03,46.65 | 45.82,28.96 59.2,28.96 63.4,33.16 63.89,33.16 65.2,34.47 71.47,34.47 74.5,31.44 v74.5,26.45 75.02,25.93 75.02,23.27 75.82,22.47 77.78,22.47 78.23,22.92 78.23,23.48 80.61,25.87 80.61,43.18 80.81,43.38 80.81,46.63 71.87,55.57 | 71.87,55.57 v73.98,55.57
N$25  (via drill 0.61 pad 1.02)  (4 unrouted)
  Top 0.178: IC3.42 44.78,22.54 45.16,22.93 46.91,22.93 48.27,21.57 v49.43,21.57 | v61.57,26.17 IC4.42 65.56,26.17 65.98,26.59 v71.31,26.59 | v27.38,46.08 26.32,46.08 24.65,47.76 23.65,47.76 IC1.42 | v71.14,49.68 72.68,49.68 72.72,49.63 IC2.42 72.72,44.01 81.47,35.26 v81.8,35.26
  Bottom 0.178: v49.43,21.57 49.43,22.47 | 49.43,22.47 49.55,22.35 57.75,22.35 v61.57,26.17 | v27.38,46.08 27.38,44.55 30.36,41.57 30.81,41.57 42.46,29.92 42.46,28.62 48.62,22.47 49.43,22.47 | JP15.7 70.32,72.01 70.32,68.5 66.8,64.98 65.17,64.98 64.59,64.4 64.23,64.4 63.66,63.83 63.66,60.75 63.42,60.52 63.42,57.39 v71.14,49.68 | v71.31,26.59 71.31,25.93 74.25,22.99 74.25,22.96 75.51,21.7 78.81,21.7 81.8,24.69 v81.8,35.26
N$26  (via drill 0.61 pad 1.02)  (4 unrouted)
  Top 0.178: IC2.37 68.72,47.13 68.28,47.13 v67.47,46.32 | IC4.37 63.48,30.17 63.34,30.31 62.88,30.31 60.62,32.56 v60.62,32.6 | v63.87,77 67.87,77 69.31,75.56 JP15.8 | IC1.37 21.37,51.76 19.6,53.54 19.6,55.53 v20.39,56.33 21.63,57.56 21.63,57.7 v19.2,60.12 | v24.63,20.21 24.79,20.05 40.48,20.05 40.78,20.35 IC3.37
  Bottom 0.178: 67.55,46.32 v67.47,46.32 | v20.39,56.33 38.57,74.5 59.43,74.5 60.56,75.63 60.56,77.69 60.85,77.98 62.89,77.98 v63.87,77 | v19.2,60.12 14.06,60.12 12.85,61.33 4.59,61.33 3.76,60.5 3.76,39.05 22.6,20.21 v24.63,20.21 | 67.55,46.32 67.55,39.03 63.5,34.98 61.72,34.98 60.62,33.88 v60.62,32.6 | 67.55,46.32 67.55,49.35 62.32,54.58 62.32,56.56 62.27,56.61 62.27,60.99 62.51,61.23 62.51,64.3 63.76,65.55 64.12,65.55 67.13,68.57 67.13,69.38 66.62,69.9 66.62,75.93 67.25,76.57 69.31,76.57 JP15.8
N$27  (via drill 0.61 pad 1.02)  (5 unrouted)
  Top 0.178: R1.2 83.33,75.56 83.33,76.66 82.43,77.55 74.85,77.55 JP15.10 | IC2.35 67.12,47.13 66.67,47.13 v66.24,46.7 | v20.42,57.55 19.21,56.35 19.21,53.24 21.49,50.96 IC1.38 | v63.4,36.01 63.48,35.93 63.48,31.77 IC4.35 65.92,31.77 v65.99,31.7 | v38.05,24.24 38.05,24.2 39.18,23.07 IC3.35
  Bottom 0.178: JP15.10 72.86,76.57 72.05,77.38 64.88,77.38 64.84,77.34 | 66.57,46.7 v66.24,46.7 | 64.84,77.34 63.82,78.36 60.69,78.36 60.17,77.84 60.17,75.79 59.28,74.89 37.76,74.89 v20.42,57.55 | 66.57,46.7 66.57,39.18 v63.4,36.01 | v38.05,24.24 37.95,24.24 36.13,22.43 36.13,21.27 47.2,10.21 47.26,10.21 52.66,15.61 54.51,15.61 57.1,18.2 57.1,19.43 66.85,29.18 66.85,30.84 v65.99,31.7 | 66.57,46.7 61.94,51.33 61.94,56.41 61.89,56.46 61.89,61.15 62.13,61.38 62.13,64.46 63.6,65.94 63.96,65.94 64.56,66.53 64.56,69.57 64.23,69.89 64.23,76.03 64.84,76.64 64.84,77.34
N$28  (via drill 0.61 pad 1.02)  (4 unrouted)
  Top 0.178: JP15.9 71.85,73.02 69.31,70.48 v67.68,70.48 | IC2.36 67.92,50.11 v67.85,50.18 | IC3.36 39.98,20.46 38.01,20.46 37.81,20.65 37.81,22.79 v38.05,23.02 | v20.41,54.08 20.41,53.72 21.57,52.56 IC1.36 | 62.15,33.4 v62.15,34.13 | IC4.36 62.76,30.97 62.15,31.58 62.15,33.4 | 62.15,33.4 60.29,33.4 59.82,32.93 59.82,32.27 62.63,29.45 v63,29.45
  Bottom 0.178: JP15.9 72.86,74.03 73.87,75.03 73.87,76.75 71.73,78.89 39.11,78.89 17.74,57.52 14.58,57.52 13.59,56.53 13.59,56.46 15.97,54.08 v20.41,54.08 | v62.15,34.13 62.33,34.31 63.38,34.31 68.27,39.21 68.27,49.76 v67.85,50.18 67.7,50.18 62.7,55.18 62.7,56.72 62.65,56.77 62.65,60.83 62.89,61.07 62.89,64.15 63.91,65.17 64.28,65.17 67.68,68.57 v67.68,70.48 | v38.05,23.02 39.59,24.57 41,24.57 42.13,23.44 42.13,21.16 47.54,15.75 50.08,15.75 53.82,19.49 56.62,19.49 63,25.87 v63,29.45
N$29  (via drill 0.61 pad 1.02)  (1 unrouted)
  Top 0.178: v69.83,65.41 69.83,65.05 71.93,62.94 v73.06,62.94 | IC2.19 68.72,61.04 v68.14,61.62
  Bottom 0.178: v73.06,62.94 74.2,62.94 80.02,57.12 80.02,52.41 90.11,42.32 91.6,42.32 91.65,42.27 91.65,41.27 93.18,39.74 JP3.1 | v69.83,65.41 68.14,63.72 v68.14,61.62
N$30  (via drill 0.61 pad 1.02)  (1 unrouted)
  Top 0.178: JP3.2 89.63,38.73 85.31,43.06 v78.11,43.06 | IC2.20 67.92,60.81 66.3,60.81 v65.86,61.26
  Bottom 0.178: v65.86,61.26 65.86,57.35 66.25,56.96 67.11,56.96 77.37,46.71 77.37,46.19 78.11,45.44 v78.11,43.06
N$31  (via drill 0.61 pad 1.02)  (1 unrouted)
  Top 0.178: v67.26,58.15 67.26,58.58 67.12,58.73 IC2.21 | JP3.3 93.18,42.28 93.72,42.28 94.57,43.12 94.57,49.17 93.49,50.25 81.61,50.25 79.22,47.86 77.5,47.86 v76.02,46.38
  Bottom 0.178: v76.02,46.38 76.02,46.98 66.85,56.14 65.99,56.14 64.24,57.89 64.24,60.25 64.43,60.44 64.43,62.12 65.57,63.27 65.57,64.28 65.62,64.32 66.97,64.32 67.26,64.03 v67.26,58.15
N$32  (via drill 0.61 pad 1.02)  (1 unrouted)
  Top 0.178: v79.63,43.87 87.04,43.87 89.63,41.27 JP3.4 | v69.21,58.25 68.52,58.25 67.3,57.03 67.24,57.03 66.32,57.95 IC2.22
  Bottom 0.178: v79.63,43.87 79.84,44.08 79.84,46.52 69.73,56.63 69.73,57.73 v69.21,58.25
N$33  (via drill 0.61 pad 1.02)  (1 unrouted)
  Top 0.178: IC2.23 65.56,57.97 65.56,58.42 v65.04,58.94 | JP3.5 92.17,43.81 91.12,44.86 v77.29,44.86
  Bottom 0.178: v65.04,58.94 65.04,57.63 66.1,56.58 66.95,56.58 76.98,46.55 76.98,45.17 v77.29,44.86
N$34  (via drill 0.61 pad 1.02)  (1 unrouted)
  Top 0.178: v72.17,63.84 72.17,64.2 70.13,66.25 68,66.25 64.9,69.34 62.09,69.34 60.63,67.88 58.26,67.88 54.81,64.43 54.81,62.04 56.29,60.56 60.08,60.56 63.48,57.17 IC2.24
  Bottom 0.178: JP3.6 90.64,44.82 80.87,54.59 80.87,57.6 74.63,63.84 v72.17,63.84
N$35
  Bottom 0.178: R2.S 89.37,51.17 90.64,49.9 JP3.10
N$36  (via drill 0.61 pad 1.02)  (1 unrouted)
  Top 0.178: IC2.31 65.56,51.57 65.56,49.5 65.05,48.99 v60.73,48.99 | R3.A 91.91,67.65 90.95,68.6 90.95,72.1 84.73,78.32 62.52,78.32 v61.37,77.17
  Bottom 0.178: v60.73,48.99 61,49.26 61,61.34 61.17,61.51 61.17,73.96 61.37,74.16 v61.37,77.17
N$37  (1 unrouted)
  Top 0.178: R4.1 R3.S
N$38  (via drill 0.61 pad 1.02)  (1 unrouted)
  Top 0.178: v70.4,45.05 57,45.05 56.18,45.88 Q1.E | JP3.9 92.17,48.89 90.76,47.48 78.28,47.48 v75.96,45.15
  Bottom 0.178: v70.4,45.05 75.86,45.05 v75.96,45.15
N$39  (via drill 0.61 pad 1.02)  (2 unrouted)
  Top 0.178: v58.09,49.35 57.95,49.35 57.18,48.57 Q1.B | R4.2 82.72,69.21 82.72,70.3 85.52,73.11 85.52,76.58 84.16,77.94 63.59,77.94 60.57,74.91 v60.57,74.5
  Bottom 0.178: v58.09,49.35 60.62,51.87 60.62,61.5 60.79,61.67 60.79,74.28 v60.57,74.5
N$40  (via drill 0.61 pad 1.02)  (1 unrouted)
  Top 0.178: IC3.21 39.18,32.05 37.97,32.05 37.59,32.44 32.79,32.44 32.12,31.77 v27.14,31.77
  Bottom 0.178: v27.14,31.77 26.76,31.38 26.76,20.82 27.14,20.43 JP7.4
N$41  (via drill 0.61 pad 1.02)  (2 unrouted)
  Top 0.178: v47.67,35.53 46.72,35.53 45.88,36.37 45.88,37.46 R5.2 | v28.27,30.03 31.23,30.03 33.26,32.05 37.24,32.05 37.63,31.67 40.53,31.67 40.78,31.92 IC3.19 v40.78,35.98 | JP4.1 51.27,9.26 46.83,13.7 v32.7,13.7
  Bottom 0.178: v32.7,13.7 32.7,18.67 28.27,23.09 v28.27,30.03 | v47.67,35.53 49.05,34.15 49.05,32.03 46.78,29.76 46.39,29.76 44.61,31.54 40.78,35.37 v40.78,35.98
N$42  (via drill 0.61 pad 1.02)  (1 unrouted)
  Top 0.178: v31.8,33.1 IC3.22
  Bottom 0.178: JP7.6 29.68,9.26 33.5,13.08 33.5,22.12 31.8,23.81 v31.8,33.1
N$43  (via drill 0.61 pad 1.02)  (2 unrouted)
  Top 0.178: TMP48.2 27.32,22.86 29.39,22.86 30.12,22.12 v36.98,22.12 | v33.4,44.77 35.63,42.54 R7.1 | JP6.1 53.81,21.56 v51.44,23.92
  Bottom 0.178: JP6.1 53.81,16.13 52.62,16.13 47.62,11.14 46.81,11.14 36.98,20.96 v36.98,22.12 | v51.44,23.92 50.2,25.17 47.7,25.17 44.61,28.26 44.61,29.92 44.14,30.39 43.75,30.39 31.65,42.49 31.65,43.09 31.23,43.51 31.23,47.41 31.27,47.46 32.46,47.46 33.4,46.52 v33.4,44.77
N$44  (via drill 0.61 pad 1.02)  (2 unrouted)
  Top 0.178: JP5.1 33.54,14.6 33.49,14.65 R6.1 32.3,15.74 32.28,15.72 v31.58,15.72 | v28.2,21.58 TMP48.1
  Bottom 0.178: v28.2,21.58 31.58,18.2 v31.58,15.72
N$45  (via drill 0.61 pad 1.02)  (1 unrouted)
  Top 0.178: IC3.1 49.22,23.3 50.24,22.29 50.24,21.21 48.73,19.7 48.73,18.15 JP5.2 | JP12.2 8.09,28.83 32.7,28.83 v33.44,28.09
  Bottom 0.178: JP5.2 48.73,18.15 47.78,18.15 42.51,23.42 42.51,23.6 35.75,30.36 34.09,30.36 33.44,29.71 v33.44,28.09
N$46  (via drill 0.61 pad 1.02)  (1 unrouted)
  Top 0.178: IC3.44 46.38,20.46 46.38,17.03 47.8,15.61 53.81,15.61 JP6.2 53.81,13.59 47.48,13.59 46.89,14.19 33.35,14.19 32.89,14.64 v24.63,14.64
  Bottom 0.178: JP12.3 8.09,31.37 9.1,31.37 24.63,15.84 v24.63,14.64
N$47  (via drill 0.61 pad 1.02)  (1 unrouted)
  Top 0.178: IC3.23 35.54,31.3 35.48,31.25 v33.95,31.25
  Bottom 0.178: JP7.8 32.22,9.26 33.88,10.92 33.88,22.27 32.22,23.94 32.22,31.21 32.25,31.25 v33.95,31.25
N$48  (via drill 0.61 pad 1.02)  (1 unrouted)
  Top 0.178: IC3.24 35.54,30.5 35.47,30.44 v33.03,30.44
  Bottom 0.178: JP7.10 34.76,9.26 34.27,9.75 34.27,22.43 32.64,24.06 32.64,30.04 v33.03,30.44
N$49  (via drill 0.61 pad 1.02)  (1 unrouted)
  Top 0.178: IC3.25 35.54,29.7 35.17,29.7 v34.64,29.17
  Bottom 0.178: JP7.12 37.3,9.26 37.3,9.87 35.37,11.8 35.37,28.45 v34.64,29.17
N$50  (via drill 0.61 pad 1.02)  (1 unrouted)
  Top 0.178: IC3.20 39.98,34.14 v25.44,34.14
  Bottom 0.178: JP7.2 24.6,9.26 25.44,10.1 v25.44,34.14
N$51  (via drill 0.61 pad 1.02)  (1 unrouted)
  Top 0.178: v35.96,9.67 37.42,9.67 38.83,8.25 JP7.14 | IC3.31 35.54,24.9 v34.56,23.92
  Bottom 0.178: v35.96,9.67 34.65,10.98 34.65,23.83 v34.56,23.92
N$52  (via drill 0.61 pad 1.02)  (1 unrouted)
  Top 0.178: v77.84,30.18 77.18,30.18 77.16,30.17 IC4.19 | v53.62,45.59 57.07,42.14 v69.84,42.14
  Bottom 0.178: JP8.1 54.82,71.75 54.82,72.76 55.57,73.51 59.46,73.51 60.36,72.62 60.36,61.78 60.23,61.65 60.23,53.91 53.62,47.3 v53.62,45.59 | v77.84,30.18 77.84,34.15 v69.84,42.14
N$53  (1 unrouted)
  Top 0.178: JP7.13 40.85,5.71 43.14,3.42 76.74,3.42 79.07,5.75 79.07,8.81 80.96,10.7 80.96,28.2 78.13,31.03 77.22,31.03 77.16,30.97 IC4.20
N$54  (1 unrouted)
  Top 0.178: JP7.11 38.31,5.71 40.98,3.03 76.89,3.03 79.45,5.6 79.45,8.64 81.35,10.54 81.35,28.37 77.94,31.77 IC4.21
N$55  (via drill 0.61 pad 1.02)  (1 unrouted)
  Top 0.178: v71.12,30.53 73.17,32.57 IC4.22
  Bottom 0.178: JP7.9 35.77,5.71 36.77,6.72 53.84,6.72 62.04,14.92 62.04,21.98 70.59,30.53 v71.12,30.53
N$56  (via drill 0.61 pad 1.02)  (1 unrouted)
  Top 0.178: v62.84,21.46 58.53,25.77 v58.53,27.47 | v71.44,32.81 71.96,33.33 74.32,33.33 IC4.23
  Bottom 0.178: v62.84,21.46 62.84,14.96 52.45,4.56 34.38,4.56 33.23,5.71 JP7.7 | v58.53,27.47 58.8,27.47 63.58,32.26 64.64,32.26 66.09,33.7 70.56,33.7 v71.44,32.81
N$57  (1 unrouted)
  Top 0.178: JP7.5 30.69,5.71 34.97,1.43 77.29,1.43 81.82,5.96 81.82,28.82 75.22,35.41 73.52,35.41 IC4.24
N$58  (via drill 0.61 pad 1.02)  (1 unrouted)
  Top 0.178: IC4.31 67.92,33.33 67.72,33.33 v66.91,32.51
  Bottom 0.178: JP7.3 28.15,5.71 29.68,7.24 48.74,7.24 49.52,8.03 49.52,9.21 49.57,9.26 51.96,9.26 61.66,18.95 61.66,22.53 68.81,29.68 68.81,32.49 68.38,32.93 67.33,32.93 v66.91,32.51
N$59  (2 unrouted)
  Top 0.178: IC3.18 41.58,34.14 41.82,34.38 41.82,36.65 41,37.46 R8.2 37.5,36.26 21.31,36.26 13.64,43.93 4.59,43.93 4.35,43.69 4.35,28.06 5.11,27.3 JP12.1
N$60  (via drill 0.61 pad 1.02)  (2 unrouted)
  Top 0.178: IC1.18 33.16,50.96 33.16,54.44 | R9.1 44.97,59.05 41.54,55.63 34.25,55.63 33.16,54.54 33.16,54.44 | v29.57,54.44 33.16,54.44
  Bottom 0.178: JP9.1 15.71,55.5 28.51,55.5 v29.57,54.44
N$61  (via drill 0.61 pad 1.02)  (2 unrouted)
  Top 0.178: JP10.1 57.62,58.04 57.75,57.91 R10.2 | IC2.18 69.52,60.81 69.52,61.37 68.43,62.47 v59.56,62.47
  Bottom 0.178: JP10.1 57.62,60.06 58.63,60.06 59.56,60.99 v59.56,62.47
N$62  (1 unrouted)
  Top 0.178: JP9.2 15.71,58.04 16.32,58.04 18.02,56.34 18.02,48.42 21.04,45.41 24.41,45.41 IC1.1
N$63  (1 unrouted)
  Top 0.178: JP9.3 15.71,60.58 16.32,60.58 18.4,58.5 18.4,49.05 21.3,46.16 IC1.44
N$64  (via drill 0.61 pad 1.02)  (1 unrouted)
  Top 0.178: JP10.2 57.62,62.6 56.61,62.6 55.84,63.37 55.84,64.74 58.56,67.46 60.75,67.46 62.25,68.96 64.74,68.96 69.11,64.59 69.74,64.59 72.28,62.05 v73.95,62.05 | IC2.1 77.16,49.97 79.2,49.97 v79.45,50.21
  Bottom 0.178: v73.95,62.05 79.45,56.55 v79.45,50.21
N$65  (via drill 0.61 pad 1.02)  (1 unrouted)
  Top 0.178: IC2.44 v74.32,46.31 v74.33,46.31 | JP10.3 64.23,64.13 v64.77,63.6
  Bottom 0.178: v74.33,46.31 74.33,48.12 66.69,55.75 65.84,55.75 63.86,57.73 63.86,60.41 64.04,60.6 64.04,62.88 v64.77,63.6
N$66  (2 unrouted)
  Top 0.178: JP11.1 R11.2 77.94,13.03 79.03,13.03 80.58,14.57 80.58,26.98 78.19,29.37 IC4.18
N$67  (via drill 0.61 pad 1.02)  (1 unrouted)
  Top 0.178: IC4.1 66.32,21.73 v65.15,21.73
  Bottom 0.178: JP11.2 79.47,6.98 79.47,7.99 77.8,9.67 76.48,9.67 65.15,21 v65.15,21.73
N$68  (via drill 0.61 pad 1.02)  (1 unrouted)
  Top 0.178: IC4.44 65.56,24.57 65.56,23.74 v65.33,23.51
  Bottom 0.178: JP11.3 82.01,6.98 82.01,7.88 77.8,12.1 74.59,12.1 65.95,20.73 65.95,22.89 v65.33,23.51
N$69  (via drill 0.61 pad 1.02)  (1 unrouted)
  Top 0.178: IC3.38 41.58,20.46 38.53,17.41 30.24,17.41 29.69,17.95 26.55,17.95 v26.29,17.69
  Bottom 0.178: v26.29,17.69 26.29,34.86 21.84,39.31 9.78,39.31 9.1,40 JP13.1
N$70  (via drill 0.61 pad 1.02)  (1 unrouted)
  Top 0.178: IC3.41 43.98,20.45 40.51,16.99 v29.52,16.99
  Bottom 0.178: v29.52,16.99 29.52,18.78 27.38,20.93 27.38,30.8 28.52,31.94 28.52,33.28 21.8,40 11.76,40 10.61,41.15 7.71,41.15 6.56,40 JP13.2
N$71  (1 unrouted)
  Top 0.178: IC3.27 35.44,28.1 34.62,27.29 25.86,27.29 24.7,28.45 6.38,28.45 6.35,28.48 6.35,34.73 7.08,35.46 7.08,40.53 8.09,41.53 JP13.3
N$72  (1 unrouted)
  Top 0.178: JP13.4 6.56,42.54 7.56,43.55 12.86,43.55 27.18,29.22 33.45,29.22 34.31,28.37 35,28.37 35.54,28.9 IC3.26
N$73  (via drill 0.61 pad 1.02)  (1 unrouted)
  Top 0.178: IC3.2 47.13,24.1 46.49,23.46 44.14,23.46 v43.7,23.9
  Bottom 0.178: JP13.5 9.1,45.08 13.01,41.16 26.03,41.16 43.29,23.9 v43.7,23.9
N$74  (via drill 0.61 pad 1.02)  (1 unrouted)
  Top 0.178: IC3.43 45.58,22.54 46.75,22.54 47.3,22 v47.3,20.39
  Bottom 0.178: JP13.6 6.56,45.08 7.56,44.07 8.98,44.07 12.67,40.39 26.26,40.39 42.89,23.76 42.89,23.57 46.08,20.39 v47.3,20.39
N$75  (via drill 0.61 pad 1.02)  (1 unrouted)
  Top 0.178: IC3.4 47.13,25.7 v45.69,24.26 | JP13.7 10.56,47.62 19.02,39.16 v32.08,39.16
  Bottom 0.178: v45.69,24.26 45.69,24.86 32.08,38.46 v32.08,39.16
N$76  (via drill 0.61 pad 1.02)  (1 unrouted)
  Top 0.178: IC3.3 49.22,24.9 50.62,23.5 v50.62,20.45
  Bottom 0.178: JP13.8 5.55,48.63 4.54,49.63 4.54,50.8 5.43,51.69 14.3,51.69 22.39,43.6 26.4,43.6 44.88,25.12 44.88,23.93 45.36,23.46 46.38,23.46 49.38,20.45 v50.62,20.45
N$77  (via drill 0.61 pad 1.02)  (1 unrouted)
  Top 0.178: IC3.5 47.13,26.5 45.89,25.25 v43.07,25.25
  Bottom 0.178: JP13.10 6.56,50.16 7.94,48.77 16.08,48.77 23.04,41.82 26.51,41.82 v43.07,25.25
N$78  (via drill 0.61 pad 1.02)  (1 unrouted)
  Top 0.178: v24.08,46.96 IC1.43
  Bottom 0.178: JP13.15 9.1,57.78 19.92,46.96 v24.08,46.96
N$79  (1 unrouted)
  Top 0.178: JP13.14 6.56,55.24 7.61,56.29 9.21,56.29 22.18,43.32 25.21,43.32 IC1.2
N$80  (1 unrouted)
  Top 0.178: IC1.3 26.01,43.32 25.63,42.93 22.03,42.93 9.72,55.24 JP13.13
N$81  (1 unrouted)
  Top 0.178: JP13.12 6.56,52.7 7.56,53.71 10.71,53.71 21.87,42.55 26.04,42.55 26.81,43.32 IC1.4
N$82  (1 unrouted)
  Top 0.178: JP13.11 9.1,52.7 19.63,42.17 26.46,42.17 27.61,43.32 IC1.5
N$83  (1 unrouted)
  Top 0.178: JP13.16 5.55,58.79 6.56,59.79 6.56,60.33 9.59,63.36 16.13,63.36 18.4,61.09 18.4,59.79 18.83,59.36 18.83,51.3 21.57,48.56 IC1.41
N$84  (via drill 0.61 pad 1.02)  (1 unrouted)
  Top 0.178: IC2.25 63.48,56.37 59.67,60.18 v52.11,60.18
  Bottom 0.178: JP13.18 6.56,60.32 7.56,59.31 9.02,59.31 15.47,52.87 24.13,52.87 24.36,53.1 28.26,53.1 28.65,52.72 31.62,52.72 34.16,55.26 51.57,55.26 52.11,55.8 v52.11,60.18
N$85  (via drill 0.61 pad 1.02)  (1 unrouted)
  Top 0.178: IC2.26 63.47,55.57 59.4,51.5 56.83,51.5 56.3,52.03 56.3,53.9 54.14,56.06 v50.78,56.06
  Bottom 0.178: JP13.17 9.1,60.32 16.16,53.25 23.97,53.25 24.21,53.49 28.42,53.49 28.8,53.1 30.53,53.1 33.48,56.06 v50.78,56.06
N$86  (via drill 0.61 pad 1.02)  (1 unrouted)
  Top 0.178: JP14.2 93.18,33.39 92.17,34.39 92.17,42.65 92.22,42.7 93.6,42.7 94.19,43.28 94.19,44.41 93.26,45.34 79.88,45.34 v79.02,46.21 | IC2.27 66.61,54.77 v68.81,56.98
  Bottom 0.178: v68.81,56.98 v68.82,56.98 68.82,56.41 v79.02,46.21
N$87  (1 unrouted)
  Top 0.178: IC2.41 71.92,47.13 71.94,47.1 71.94,43.78 83.34,32.38 89.63,32.38 JP14.1
N$88  (via drill 0.61 pad 1.02)  (1 unrouted)
  Top 0.178: IC2.38 69.52,46.81 v69.86,46.47 | JP14.4 92.17,29.84 90.78,31.23 82.44,31.23 v78.59,35.07
  Bottom 0.178: v69.86,46.47 69.6,46.21 69.6,44.07 v78.59,35.07
N$89  (via drill 0.61 pad 1.02)  (1 unrouted)
  Top 0.178: IC2.43 73.52,43.75 80.66,36.61 v83.97,36.61
  Bottom 0.178: JP14.3 90.64,30.85 89.74,30.85 v83.97,36.61
N$90  (1 unrouted)
  Top 0.178: IC2.2 75.08,50.77 75.08,46.7 75.16,46.62 75.16,44.64 79.6,40.2 84.36,40.2 91.65,32.91 91.65,31.9 92.51,31.04 93.52,31.04 94.19,30.37 94.19,29.31 93.18,28.31 JP14.6
N$91  (via drill 0.61 pad 1.02)  (1 unrouted)
  Top 0.178: IC2.3 77.16,51.57 77.55,51.57 v77.59,51.53
  Bottom 0.178: JP14.5 90.64,28.31 81.58,37.37 81.58,46.94 77.59,50.93 v77.59,51.53
N$92  (1 unrouted)
  Top 0.178: JP14.7 91.65,24.76 92.67,23.73 94.53,23.73 95.76,24.97 95.76,49.06 91.65,53.17 IC2.5
N$93  (1 unrouted)
  Top 0.178: JP14.8 93.18,25.77 95.05,27.64 95.05,49.23 91.91,52.37 IC2.4
N$94  (1 unrouted)
  Top 0.178: IC4.25 72.72,35.41 73.1,35.8 75.38,35.8 90.49,20.69 91.64,20.69 91.69,20.64 91.69,19.2 92.22,18.67 94.15,18.67 94.2,18.72 94.2,21.2 JP14.10
N$95  (1 unrouted)
  Top 0.178: IC4.26 71.92,35.41 72.69,36.18 75.54,36.18 89.5,22.22 89.63,22.22 JP14.9
N$96  (1 unrouted)
  Top 0.178: IC4.27 71.12,35.41 72.27,36.56 75.7,36.56 88.99,23.27 91.6,23.27 91.65,23.22 91.65,22.22 93.18,20.69 JP14.12
N$97  (via drill 0.61 pad 1.02)  (1 unrouted)
  Top 0.178: IC4.41 69.89,26.97 v70.31,27.4
  Bottom 0.178: v70.31,27.4 70.01,27.09 70.01,24.96 75.29,19.68 JP14.11
N$98  (via drill 0.61 pad 1.02)  (1 unrouted)
  Top 0.178: v68.8,25.51 65.7,25.51 65.56,25.37 IC4.43
  Bottom 0.178: JP14.14 92.17,17.14 90.78,18.53 75.78,18.53 v68.8,25.51
N$99  (via drill 0.61 pad 1.02)  (1 unrouted)
  Top 0.178: v67.61,21.29 67.17,21.73 67.12,21.73 IC4.2
  Bottom 0.178: JP14.13 92.13,15.65 94.14,15.65 94.19,15.6 94.19,14.18 93.38,13.38 75.53,13.38 v67.61,21.29
N$100  (via drill 0.61 pad 1.02)  (1 unrouted)
  Top 0.178: IC4.3 67.92,23.81 67.03,24.7 v66.4,24.7
  Bottom 0.178: v66.4,24.7 65.35,24.7 64.29,23.64 64.29,17.91 76.93,5.26 85.38,5.26 92.17,12.06 JP14.18
N$101  (via drill 0.61 pad 1.02)  (1 unrouted)
  Top 0.178: v70.81,25.29 69.99,25.29 68.72,24.02 IC4.4 | JP14.17 90.64,13.07 83.21,20.49 v82.64,20.49
  Bottom 0.178: v70.81,25.29 75.61,20.49 v82.64,20.49
N$102  (via drill 0.61 pad 1.02)  (1 unrouted)
  Top 0.178: v69.34,21.31 69.34,21.54 69.52,21.73 IC4.5
  Bottom 0.178: JP14.15 76.05,14.6 v69.34,21.31
N$103  (via drill 0.61 pad 1.02)  (1 unrouted)
  Top 0.178: v65.98,29.68 65.68,29.37 IC4.38
  Bottom 0.178: JP13.9 15.24,50.16 22.47,42.92 26.54,42.92 44.5,24.96 44.5,23.77 45.2,23.07 45.98,23.07 49.87,19.18 51.05,19.18 51.79,19.93 56.52,19.93 62.38,25.79 62.38,28.92 61.89,29.41 61.89,29.48 62.88,30.47 65.19,30.47 v65.98,29.68
N$104  (via drill 0.61 pad 1.02)  (1 unrouted)
  Top 0.178: v25.09,51.92 26.01,52.84 IC1.31
  Bottom 0.178: JP14.16 92.17,14.6 91.02,15.75 76.99,15.75 67.98,24.77 67.98,26.24 72.25,30.51 72.25,30.58 69.51,33.32 66.24,33.32 64.8,31.87 63.74,31.87 59.34,27.47 59.34,27.14 54.93,22.74 49.86,22.74 48.68,23.92 47.71,23.92 42.84,28.78 42.84,30.08 30.97,41.96 30.51,41.96 28.18,44.29 28.18,46.84 28.14,46.89 26.36,46.89 25.99,46.52 25.92,46.52 25.09,47.36 v25.09,51.92
VCC  (via drill 0.61 pad 1.02)  (24 unrouted)
  Top 0.498: 28.49,55.79 28.49,55.88 IC1.28 | 28.32,54.73 28.32,55.01 28.41,55.11 | 76.22,28.65 76.21,28.65 76.13,28.57
  Top 0.533: TMP48.8 22.3,21.58 22.3,21.14 24.77,18.67 | 50.13,59.05 R9.2 | R8.1 37.17,37.46 37.17,39.79 | R7.2 41.24,42.54 41.24,41.27 39.76,39.79 | JP15.13 JP15.11 74.22,73.02 74.22,69.27 | JP8.2 57.53,71.75 57.53,70.68 58.72,69.49 | 77.94,15.36 R11.1 77.94,15.36 | 62.7,5.71 JP4.2 51.27,6.89 37.53,6.89 | 62.7,5.71 QG1.4 | J1.1 7.84,6.98 7.84,5.25 9.11,3.98 18.96,3.98 21.88,6.89 | 62.7,5.71 72.99,16 | IC4.7 71.12,17.87 72.99,16 | 74.22,69.27 83.55,59.93 | R2.E 85.18,61.57 83.55,59.93 | 28.49,55.79 28.49,55.18 28.41,55.11 | 54.95,51.54 R10.1 53.68,52.7 52.56,52.7 50.3,54.96 | 54.95,51.54 54.95,51.33 53.98,50.36 53.98,48.59 Q1.C 53.98,46.65 57.32,43.31 70.56,43.31 | IC3.28 37.8,27.3 39.35,28.84 42.38,28.84 | 76.13,28.57 IC4.17 71.05,28.57 70.14,29.47 | 72.99,16 77.3,16 | 77.3,16 77.94,15.36 | 42.38,28.84 42.38,31.88 IC3.17 42.38,37.16 39.76,39.79 | 21.88,6.89 37.53,6.89 | 37.17,39.79 39.76,39.79 | 30.22,50.85 30.91,50.16 IC1.17 35.43,50.16 36.34,51.06 38.99,51.06 39.31,50.74 46.09,50.74 50.3,54.96 | 54.95,51.54 55.77,50.71 59.58,50.71 62.84,53.97 IC2.28 67.2,53.97 70.32,57.09 70.32,58.55 IC2.17 | 42.38,28.84 43.57,27.65 46.26,27.65 46.71,28.1 IC3.7 | 30.22,50.85 30.22,50.96 28.32,52.86 28.32,54.73 | R6.2 32.12,18.54 31.98,18.67 24.77,18.67 | 50.13,59.05 50.13,56.8 49.8,56.47 49.8,55.46 50.3,54.96 | 28.73,49.36 IC1.40 | 30.22,50.85 28.73,49.36 | 37.53,6.89 37.53,6.9 42.24,6.9 v47.3,11.96 | 70.56,43.31 70.83,43.04 70.83,40.96 70.32,40.46 IC4.28 70.32,31.11 70.14,30.93 70.14,29.47 | 24.77,18.67 21.88,15.78 21.88,6.89 | 28.73,49.36 28.73,47.44 29.21,46.97 IC1.7 29.21,42.44 29.87,41.78 35.18,41.78 37.17,39.79
  Top 0.533: IC3.40 43.18,23.04 42.49,23.73 v40.7,23.73 | 70.56,43.31 71.38,44.13 71.38,45.46 71.12,45.72 IC2.40 | 76.22,28.65 78.12,28.65 80.02,26.75 80.02,18.72 77.3,16 | 70.14,29.47 68.44,27.77 IC4.40 | 58.72,69.49 50.13,60.91 50.13,59.05 | IC2.7 78.39,54.77 83.55,59.93 | 74.22,69.27 67.5,69.27 66.48,70.29 59.85,70.29 59.24,69.67 58.89,69.67 58.72,69.49
  Bottom 0.533: R2.E 91.91,59.21 90.31,57.62 90.31,54.75 91.91,53.16 91.91,48.31 92.69,47.53 93.18,47.53 JP3.7 | v40.7,23.73 40.7,18.56 v47.3,11.96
